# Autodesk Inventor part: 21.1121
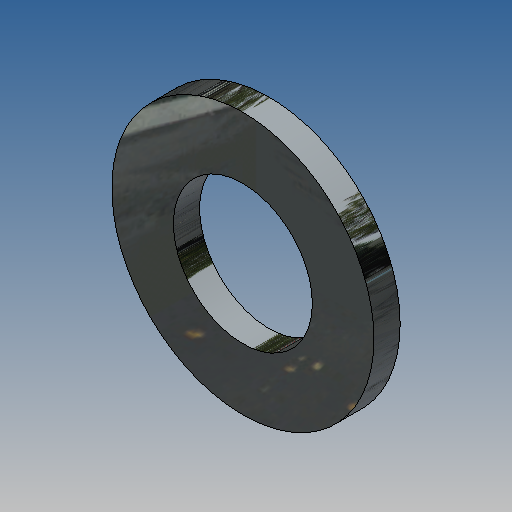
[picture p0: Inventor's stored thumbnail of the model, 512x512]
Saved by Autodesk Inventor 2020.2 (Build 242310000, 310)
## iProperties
Created: 2012-10
Part Number: 21.1121
Document SubType Name: Modeling
Designer: Administrator
Density: 7.85 g/cm^3
Material: Steel
Description: WASHER M5 Zinc Plated DIN 125-1 A
Mass: 0.119485 g
Surface Area: 0.769062 cm^2
Volume: 0.015221 cm^3
Appearance: Zinc
Author: Administrator
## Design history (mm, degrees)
sketch "Sketch1"
  geometry: C1 r 2.65 at (0, 0); C2 r 5 at (0, 0); 1 further point
  constraints: 2 centre point, 2 coincident
  dimensions: "d0" = 5.3 diameter of C1; "d1" = 10 diameter of C2
extrude "Extrusion1" new body sketch "Sketch1" distance "d2" = 1; taper "d3" = 0 deg
body "Solid1"
